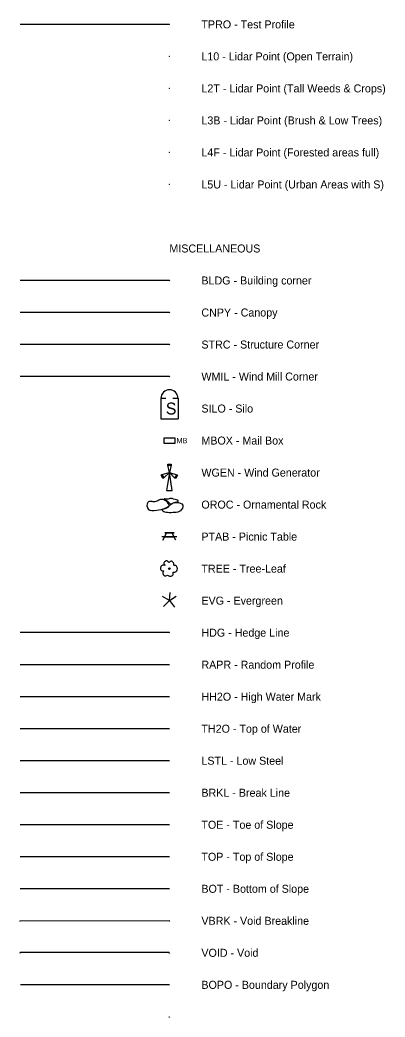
# Model space of a CAD drawing. Extents: x 2147716 to 2176321, y 2125040 to 2131750.
# Drawn here: x 2175978 to 2176321, y 2127278 to 2128212 of the extents above; entities that cross this region are included whole.
import ezdxf

# ---------------------------------------------------------------- set-up
doc = ezdxf.new("R2010")
doc.units = 0
for name, color, linetype in [('BLDG INP', 7, 'Continuous'), ('BRKLN', 7, 'Continuous'), ('Default', 7, 'Continuous'), ('HYD INP', 7, 'Continuous'), ('MANMD STRU INP', 7, 'Continuous'), ('PHO CTRL', 7, 'Continuous'), ('SPOT', 7, 'Continuous'), ('VEG INP', 7, 'Continuous'), ('VOID', 7, 'Continuous')]:
    doc.layers.add(name, color=color, linetype=linetype)

msp = doc.modelspace()

# ---------------------------------------------------------------- linework, layer by layer
at = {"layer": 'BLDG INP'}
for p, q in [((2176118.6, 2127967.97), (2175978.6, 2127967.97)), ((2176118.5, 2127967.77), (2176118.7, 2127968.17)), ((2176118.5, 2127968.17), (2176118.7, 2127967.77))]:
    msp.add_line(p, q, dxfattribs=at)
at = {"layer": 'BRKLN'}
for p, q in [((2176118.6, 2127607.97), (2175978.6, 2127607.97)), ((2176118.6, 2127487.97), (2175978.6, 2127487.97)), ((2176118.6, 2127457.97), (2175978.6, 2127457.97)), ((2176118.6, 2127427.97), (2175978.6, 2127427.97)), ((2176118.6, 2127397.97), (2175978.6, 2127397.97)), ((2176118.6, 2127307.97), (2175978.9, 2127307.97))]:
    msp.add_line(p, q, dxfattribs=at)
at = {"layer": 'Default'}
for p, q in [((2176118.6, 2127577.97), (2175978.6, 2127577.97)), ((2176118.6, 2127517.97), (2175978.6, 2127517.97))]:
    msp.add_line(p, q, dxfattribs=at)
at = {"layer": 'HYD INP'}
msp.add_line((2176118.6, 2127547.97), (2175978.6, 2127547.97), dxfattribs=at)
at = {"layer": 'MANMD STRU INP'}
for p, q in [((2176118.6, 2127937.97), (2175978.6, 2127937.97)), ((2176118.5, 2127937.77), (2176118.7, 2127938.17)), ((2176118.5, 2127938.17), (2176118.7, 2127937.77)), ((2176118.6, 2127907.97), (2175978.6, 2127907.97)), ((2176118.5, 2127907.77), (2176118.7, 2127908.17)), ((2176118.5, 2127908.17), (2176118.7, 2127907.77)), ((2176118.6, 2127877.97), (2175978.6, 2127877.97)), ((2176118.5, 2127877.77), (2176118.7, 2127878.17)), ((2176118.5, 2127878.17), (2176118.7, 2127877.77)), ((2176110.7, 2127857.57), (2176110.7, 2127838.37)), ((2176110.7, 2127857.57), (2176115.3, 2127857.57)), ((2176121.9, 2127857.57), (2176126.7, 2127857.57)), ((2176126.7, 2127857.57), (2176126.7, 2127838.37)), ((2176118.7, 2127847.97), (2176118.7, 2127847.97)), ((2176110.7, 2127838.37), (2176126.7, 2127838.37)), ((2176120.9, 2127819.57), (2176120.9, 2127819.57)), ((2176112.5, 2127724.57), (2176116.1, 2127731.77)), ((2176114.2, 2127731.77), (2176123, 2127731.77)), ((2176114.2, 2127731.47), (2176123, 2127731.47)), ((2176124.6, 2127724.57), (2176121, 2127731.77)), ((2176111.5, 2127727.97), (2176125.6, 2127727.97)), ((2176114.2, 2127727.77), (2176123, 2127727.77))]:
    msp.add_line(p, q, dxfattribs=at)
for points in [[(2176113.6, 2127820.57), (2176123.6, 2127820.57), (2176123.6, 2127815.37), (2176113.6, 2127815.37)], [(2176117, 2127795.87), (2176120.4, 2127795.87), (2176120.4, 2127795.07), (2176117, 2127795.07)], [(2176118.6, 2127787.97), (2176117, 2127795.07), (2176120.4, 2127795.07)], [(2176112.6, 2127782.57), (2176110.8, 2127785.57), (2176111.6, 2127786.07), (2176113.4, 2127783.07)], [(2176118.6, 2127787.97), (2176113.4, 2127783.07), (2176111.6, 2127786.07)], [(2176118.6, 2127787.97), (2176116, 2127771.27), (2176121.2, 2127771.27)], [(2176118.6, 2127787.97), (2176125.5, 2127785.87), (2176123.8, 2127782.87)], [(2176126.2, 2127785.47), (2176124.6, 2127782.47), (2176123.8, 2127782.87), (2176125.5, 2127785.87)]]:
    msp.add_lwpolyline(points, close=True, dxfattribs=at)
msp.add_arc((2176118.66, 2127857.55), 8, 0, 180, dxfattribs=at)
for points in [[(2176108.7, 2127762.17), (2176105.1, 2127760.57), (2176101.7, 2127760.97), (2176098.4, 2127759.97), (2176098.7, 2127753.77), (2176106.7, 2127752.87), (2176118.3, 2127757.37), (2176113.5, 2127762.37), (2176110.2, 2127762.67), (2176108.6, 2127762.07)], [(2176111.9, 2127753.47), (2176117.2, 2127755.87), (2176120.2, 2127758.27), (2176125.3, 2127759.97), (2176131.1, 2127757.47), (2176129, 2127752.17), (2176123.7, 2127750.57), (2176116.7, 2127750.47), (2176112.5, 2127751.87), (2176111.7, 2127753.27)], [(2176113.9, 2127762.87), (2176117.6, 2127760.57), (2176119.5, 2127758.67), (2176120.1, 2127758.57), (2176122.1, 2127759.77), (2176124.1, 2127760.17), (2176125.8, 2127760.47), (2176126.9, 2127761.27), (2176124.1, 2127762.67), (2176119.1, 2127763.77), (2176114.9, 2127763.17), (2176113.7, 2127763.27), (2176113.8, 2127762.97), (2176114.1, 2127762.67)]]:
    msp.add_spline(points, degree=3, dxfattribs=at)
at = {"layer": 'PHO CTRL'}
for p, q in [((2176118.6, 2128207.97), (2175978.6, 2128207.97)), ((2176118.5, 2128207.77), (2176118.7, 2128208.17)), ((2176118.5, 2128208.17), (2176118.7, 2128207.77)), ((2176118.5, 2128177.77), (2176118.7, 2128178.17)), ((2176118.5, 2128178.17), (2176118.7, 2128177.77)), ((2176118.5, 2128147.77), (2176118.7, 2128148.17)), ((2176118.5, 2128148.17), (2176118.7, 2128147.77)), ((2176118.5, 2128117.77), (2176118.7, 2128118.17)), ((2176118.5, 2128118.17), (2176118.7, 2128117.77)), ((2176118.5, 2128087.77), (2176118.7, 2128088.17)), ((2176118.5, 2128088.17), (2176118.7, 2128087.77)), ((2176118.5, 2128057.77), (2176118.7, 2128058.17)), ((2176118.5, 2128058.17), (2176118.7, 2128057.77))]:
    msp.add_line(p, q, dxfattribs=at)
at = {"layer": 'SPOT'}
for p, q in [((2176118.5, 2127277.77), (2176118.7, 2127278.17)), ((2176118.5, 2127278.17), (2176118.7, 2127277.77))]:
    msp.add_line(p, q, dxfattribs=at)
at = {"layer": 'VEG INP'}
for p, q in [((2176118.6, 2127667.97), (2176119.2, 2127675.47)), ((2176118.6, 2127667.97), (2176124.9, 2127672.17)), ((2176118.6, 2127667.97), (2176112, 2127671.87)), ((2176118.6, 2127667.97), (2176113.2, 2127662.57)), ((2176118.6, 2127667.97), (2176123.4, 2127661.97)), ((2176118.6, 2127637.97), (2175978.6, 2127637.97)), ((2176118.5, 2127637.77), (2176118.7, 2127638.17)), ((2176118.5, 2127638.17), (2176118.7, 2127637.77))]:
    msp.add_line(p, q, dxfattribs=at)
msp.add_circle((2176118.6, 2127697.97), 0.703, dxfattribs=at)
msp.add_spline([(2176118, 2127703.67), (2176119.2, 2127704.57), (2176121, 2127704.87), (2176121.9, 2127703.97), (2176122.8, 2127702.77), (2176122.8, 2127701.27), (2176124, 2127700.97), (2176125.2, 2127700.37), (2176125.8, 2127699.17), (2176126.1, 2127697.97), (2176125.5, 2127695.87), (2176124.3, 2127694.97), (2176123.1, 2127694.67), (2176122.2, 2127694.67), (2176122.2, 2127693.17), (2176121.9, 2127691.97), (2176121, 2127691.07), (2176119.2, 2127690.77), (2176118, 2127691.07), (2176116.8, 2127691.97), (2176115.3, 2127691.07), (2176114.1, 2127691.37), (2176112.9, 2127692.27), (2176112.6, 2127693.47), (2176112.6, 2127694.67), (2176113.5, 2127695.57), (2176112, 2127695.87), (2176110.5, 2127696.77), (2176110.2, 2127697.97), (2176110.5, 2127699.47), (2176110.8, 2127700.37), (2176111.7, 2127700.97), (2176112.6, 2127701.27), (2176113.5, 2127701.27), (2176114.4, 2127700.97), (2176113.8, 2127702.17), (2176113.5, 2127703.37), (2176114.1, 2127704.27), (2176115.3, 2127705.17), (2176116.5, 2127705.17), (2176117.4, 2127704.57), (2176117.7, 2127704.27), (2176118, 2127703.67)], degree=3, dxfattribs=at)
at = {"layer": 'VOID'}
for p, q in [((2175978.5, 2127367.77), (2175978.7, 2127368.17)), ((2175978.5, 2127368.17), (2175978.7, 2127367.77)), ((2176118.6, 2127367.97), (2175978.7, 2127367.77)), ((2176118.5, 2127367.77), (2176118.7, 2127368.17)), ((2176118.5, 2127368.17), (2176118.7, 2127367.77)), ((2175978.6, 2127337.77), (2175978.8, 2127338.17)), ((2175978.6, 2127338.17), (2175978.8, 2127337.77)), ((2176118.5, 2127338.17), (2175978.8, 2127338.17)), ((2176118.5, 2127337.77), (2176118.7, 2127338.17)), ((2176118.5, 2127338.17), (2176118.7, 2127337.77))]:
    msp.add_line(p, q, dxfattribs=at)

# ---------------------------------------------------------------- texts
at = {"layer": 'Default'}
for s, p in [('TPRO - Test Profile', (2176148.6, 2128204.22)), ('L10 - Lidar Point (Open Terrain)', (2176148.6, 2128174.22)), ('L2T - Lidar Point (Tall Weeds & Crops)', (2176148.6, 2128144.22)), ('L3B - Lidar Point (Brush & Low Trees)', (2176148.6, 2128114.22)), ('L4F - Lidar Point (Forested areas full)', (2176148.6, 2128084.22)), ('L5U - Lidar Point (Urban Areas with S)', (2176148.6, 2128054.22)), ('MISCELLANEOUS', (2176118.6, 2127994.22)), ('BLDG - Building corner', (2176148.6, 2127964.22)), ('CNPY - Canopy', (2176148.6, 2127934.22)), ('STRC - Structure Corner', (2176148.6, 2127904.22)), ('WMIL - Wind Mill Corner', (2176148.6, 2127874.22)), ('SILO - Silo', (2176148.6, 2127844.22)), ('MBOX - Mail Box', (2176148.6, 2127814.22)), ('WGEN - Wind Generator', (2176148.6, 2127784.22)), ('OROC - Ornamental Rock', (2176148.6, 2127754.22)), ('PTAB - Picnic Table', (2176148.6, 2127724.22)), ('TREE - Tree-Leaf', (2176148.6, 2127694.22)), ('EVG - Evergreen', (2176148.6, 2127664.22)), ('HDG - Hedge Line', (2176148.6, 2127634.22)), ('RAPR - Random Profile', (2176148.6, 2127604.22)), ('HH2O - High Water Mark', (2176148.6, 2127574.22)), ('TH2O - Top of Water', (2176148.6, 2127544.22)), ('LSTL - Low Steel', (2176148.6, 2127514.22)), ('BRKL - Break Line', (2176148.6, 2127484.22)), ('TOE - Toe of Slope', (2176148.6, 2127454.22)), ('TOP - Top of Slope', (2176148.6, 2127424.22)), ('BOT - Bottom of Slope', (2176148.6, 2127394.22)), ('VBRK - Void Breakline', (2176148.6, 2127364.22)), ('VOID - Void', (2176148.6, 2127334.22)), ('BOPO - Boundary Polygon', (2176148.6, 2127304.22))]:
    msp.add_text(s, height=7.5, dxfattribs=at).set_placement(p)
at = {"layer": 'MANMD STRU INP'}
for s, height, p in [('S', 11.2, (2176115.2, 2127842.37)), ('MB', 5, (2176125.2, 2127815.47))]:
    msp.add_text(s, height=height, dxfattribs=at).set_placement(p)

doc.saveas('drawing.dxf')
